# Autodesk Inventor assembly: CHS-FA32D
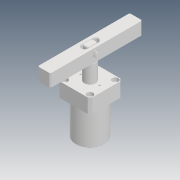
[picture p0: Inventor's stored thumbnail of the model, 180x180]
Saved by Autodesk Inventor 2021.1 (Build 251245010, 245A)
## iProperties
Created: 2019-04
Part Number: CHS-FA32D
Description: STEP AP203
Document SubType Name: Assembly
Designer: user
Title: chs-fa32d_asm.STEP
Revision Number: ÈÎºÎ
Sending System: SolidWorks 2017
Preprocessor: SwSTEP 2.0
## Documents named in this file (6)
- D:\Vault_2016\Projekty\Clamptek\Hydraulic\CHS\CHS-32\Inventor\CHS-FA32D\CHS-FA32D.iam
- D:\Vault_2016\Projekty\Clamptek\Hydraulic\CHS\CHS-32\Inventor\CHS-FA32D\CHS-32D-02_1_1.ipt
- D:\Vault_2016\Projekty\Clamptek\Hydraulic\CHS\CHS-32\Inventor\CHS-FA32D\CHS-32D-01_2.ipt
- D:\Vault_2016\Projekty\Clamptek\Hydraulic\CHS\CHS-32\Inventor\CHS-FA32D\Öá8µ²È¦_1.ipt
- D:\Vault_2016\Projekty\Clamptek\Hydraulic\CHS\CHS-32\Inventor\CHS-FA32D\Xiaozhou_1.ipt
- D:\Vault_2016\Projekty\Clamptek\Hydraulic\CHS\CHS-32\Inventor\CHS-FA32D\CHS-FA32BT.ipt
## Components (6 placed, 6 different names)
1. CHS-32D-02_1_1_1
2. CHS-32D-01_2_2
3. Öá8µ²È¦_1_3
4. Xiaozhou_1_4
5. Öá8µ²È¦_1_5
6. CHS-FA32BT_6
